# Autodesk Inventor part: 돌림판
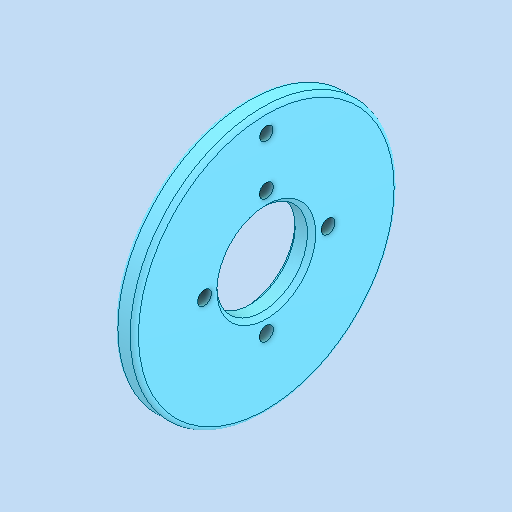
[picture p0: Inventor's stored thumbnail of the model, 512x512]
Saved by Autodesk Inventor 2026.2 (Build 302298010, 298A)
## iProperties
Created: 2026-08
Part Number: 돌림판
Material: 강철, 연강
Document SubType Name: Modeling
Designer: PC2-02
Density: 7.85 g/cm^3
Appearance: 기본값
Author: jhkim
Sending System: Autodesk Inventor 2027
Preprocessor: ST-DEVELOPER v20.1
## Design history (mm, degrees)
feature "솔리드1"
node "솔리드2"
